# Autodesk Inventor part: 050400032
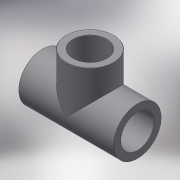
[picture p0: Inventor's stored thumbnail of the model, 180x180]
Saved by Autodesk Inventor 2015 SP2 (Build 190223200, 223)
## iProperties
Created: 2017-10
Part Number: 050400032
Material: Generic
Description: PLASSON TEE-CEMENT PVC 32
Document SubType Name: Modeling
Designer: KIM
Density: 1 g/cm^3
Appearance: Default
Author: KIM
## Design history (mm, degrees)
derived "050400.ipt"
feature "Solid1::050400.ipt"
feature "Solid2::050400.ipt"
tag "TaggingFeature1"
body "Solid1"
other parameters: "d0" = 78, "d2" = 22, "d4" = 32, "d5" = 28.8, "d7" = 0.32, "d8" = 22, "d9" = 39, "d11" = 32, "d12" = 28.8, "d15" = 0, "d17" = 0, "d18" = 32, "d19" = 28.8, "d20" = 32, "d21" = 22, "d22" = 0, "d23" = 22, "d24" = 0.32, "d_" = 32, "H_" = 78, "l_" = 22, "Z_" = 17
